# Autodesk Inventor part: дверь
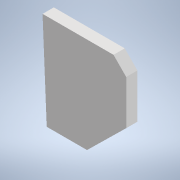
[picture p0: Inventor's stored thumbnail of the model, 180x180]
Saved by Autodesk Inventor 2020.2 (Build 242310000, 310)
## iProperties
Created: 2020-04
Part Number: дверь
Material: Типовые
Document SubType Name: Modeling
Designer: Алексей
Density: 1 g/cm^3
Appearance: По умолчанию
Author: Алексей
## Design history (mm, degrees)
sketch "Эскиз1"
  geometry: L1 (11, -78)-(4.414, -78) reference; L2 (11, -78)-(11, -74) reference; L3 (11, -74)-(25, -74) reference; L4 (25, -74)-(25, -78) reference; L5 (35, -78)-(25, -78) reference; L6 (35, -58)-(35, -78) reference; L7 (28.375, -58)-(35, -58) reference; L8 (35, -18)-(28.375, -18) reference; L9 (35, -2)-(35, -18) reference; L10 (35, -2)-(31, -2) reference; L11 (31, -2)-(31, 12) reference; L12 (31, 12)-(35, 12) reference; L13 (35, 28)-(35, 12) reference; L14 (28.375, 28)-(35, 28) reference; L15 (35, 68)-(28.375, 68) reference; L16 (35, 78)-(35, 68) reference; L17 (22, 78)-(35, 78) reference; L18 (22, 78)-(22, 74) reference; L19 (22, 74)-(8, 74) reference; L20 (8, 74)-(8, 78) reference; L21 (-5, 78)-(8, 78) reference; L22 (-7.718, 70.105)-(-5, 78) reference; L23 (-12.5, 67)-(-7.718, 70.105) reference; L24 (-13.093, 60.719)-(-12.5, 67) reference; L25 (-13.093, 60.719)-(-9.11, 60.343) reference; L26 (-9.11, 60.343)-(-10.425, 46.405) reference; L27 (-10.425, 46.405)-(-14.407, 46.781) reference; L28 (-15, 40.5)-(-14.407, 46.781) reference; L29 (-4.88, 34.8)-(-15, 40.5) reference; L30 (-2.58, 25.5)-(-4.88, 34.8) reference; L31 (-15.736, -18.735)-(-8.938, -18.9) reference; L32 (-34.328, -10.306)-(-15.736, -18.735) reference; L33 (-35, -16.306)-(-34.328, -10.306) reference; L34 (-26.476, -21.507)-(-35, -16.306) reference; L35 (-26.476, -21.507)-(-24.392, -18.092) reference; L36 (-24.392, -18.092)-(-12.441, -25.384) reference; L37 (-12.441, -25.384)-(-14.524, -28.799) reference; L38 (-6, -34)-(-14.524, -28.799) reference; L39 (-3.6, -49.087)-(-6, -34) reference; L40 (-3.6, -49.087)-(0.351, -48.458) reference; L41 (0.351, -48.458)-(2.55, -62.285) reference; L42 (2.55, -62.285)-(-1.4, -62.913) reference; L43 (0.464, -74.628)-(-1.4, -62.913) reference; L44 (15.516, 69.015)-(18.321, 66.163) reference; L45 (15.516, 69.015)-(4.375, 58.059) reference; L46 (4.375, 58.059)-(4.375, 38.177) reference; L47 (4.375, 38.177)-(25.343, 16.854) reference; L48 (25.343, 16.854)-(25.343, -7.321) reference; L49 (25.343, -7.321)-(4.375, -27.941) reference; L50 (4.375, -27.941)-(4.375, -56) reference; L51 (8.375, -56)-(4.375, -56) reference; L52 (8.375, -56)-(8.375, -29.617) reference; L53 (8.375, -29.617)-(30.337, -8.02) reference; L54 (30.337, -8.02)-(30.337, 17.48) reference; L55 (30.337, 17.48)-(8.375, 39.814) reference; L56 (8.375, 39.814)-(8.375, 56.383) reference; L57 (8.375, 56.383)-(18.321, 66.163) reference; L58 (-8.938, -18.9)-(6.438, -18.9); L59 (6.438, -18.9)-(20.343, -5.226); L60 (20.343, -5.226)-(20.343, 10.529); L61 (20.343, 10.529)-(15.848, 15.1); L62 (15.848, 15.1)-(-11.68, 15.1); L63 (-2.58, 25.5)-(15.848, 15.1) reference; L64 (15.848, 15.1)-(20.343, 10.529) reference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; A1 r 4 centre (4.414, -74) between (0.464, -74.628) and (4.414, -78) reference; A2 r 20 centre (28.375, -38) between (28.375, -18) and (28.375, -58) reference; A3 r 20 centre (28.375, 48) between (28.375, 68) and (28.375, 28) reference; 1 further point
  constraints: 10 end point, 3 parallel, 2 horizontal, 1 perpendicular
  dimensions: "d0" = 5 distance between parallel lines of L49 L59; "d1" = 5 distance between parallel lines of L48 L60; "d2" = 8 distance between parallel lines of L47 L61
extrude "Выдавливание1" new body sketch "Эскиз1" distance "d3" = 2; taper "d4" = 0 deg
node "Твердое тело1"
node "Ссылка1"
node "Ссылка3"
